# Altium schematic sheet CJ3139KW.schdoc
size 127 x 101 mm
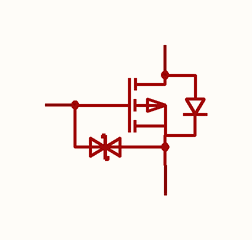
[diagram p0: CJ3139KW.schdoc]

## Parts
Q?  cj3139kw  [SOT-323-3_L2.1-W1.3-P1.30-LS2.3-BR]  (value not drawn)

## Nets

Not connected (* = marked no-connect by the designer): Q? 1(G) 2(S) 3(D)

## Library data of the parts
Q? = cj3139kw: 数量:1个P沟道;漏源电压(Vdss):20V;连续漏极电流(Id):660mA;导通电阻(RDS(on)):520mΩ@4.5V;耗散功率(Pd):200mW;阈值电压(Vgs(th)):450mV;; Manufacturer: CJ(江苏长电/长晶); AddInBom: yes; ModelId: 81bbbbdf3145418d8c918b8f2fd0a837; ModelTransform: 90.551,78.74,0,0,0,0,0,0,0; Number: 1个P沟道; Drain to Source Voltage: 20V; Current - Continuous Drain(Id): 660mA; Pd - Power Dissipation: 200mW; Gate Threshold Voltage (Vgs(th)): 450mV; Input Capacitance(Ciss): 170pF; Reverse Transfer Capacitance (Crss@Vds): 15pF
